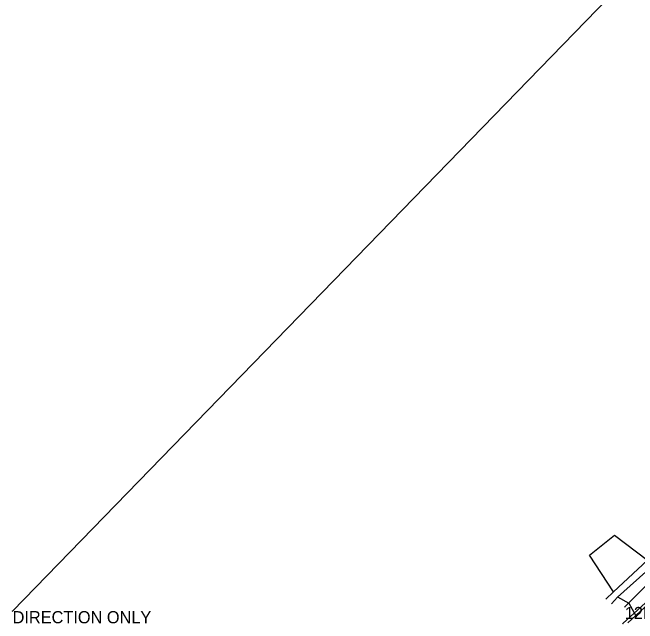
# Model space of a CAD drawing. Extents: x 1660112 to 1662239, y 668919 to 671377.
# Drawn here: x 1660996.9 to 1661253.1, y 669845.5 to 670095.9 of the extents above; entities that cross this region are included whole.
import ezdxf

# ---------------------------------------------------------------- set-up
doc = ezdxf.new("R2010")
doc.units = 0
for name, color, linetype in [('R_Horz Alg', 7, 'Continuous'), ('S_DRG_PT_SYM', 7, 'Continuous'), ('S_DRIVEWAY', 7, 'Continuous'), ('S_EDGE_PAVEMENT', 7, 'Continuous'), ('S_SANITARY_SEWER', 7, 'Continuous'), ('S_SANITARY_SEWER_ANNOT', 7, 'Continuous'), ('S_SIDE_DRAIN', 7, 'Continuous'), ('S_SIDE_DRAIN_ANNOT', 7, 'Continuous'), ('S_SIDEWALK', 7, 'Continuous'), ('S_UTL_PT_SYM', 7, 'Continuous'), ('S_WATER_UTILITIES', 7, 'Continuous')]:
    doc.layers.add(name, color=color, linetype=linetype)

msp = doc.modelspace()

# ---------------------------------------------------------------- linework, layer by layer
at = {"layer": 'R_Horz Alg'}
msp.add_arc((1655846.99, 664877.91), 7639.44, 42.561815, 45.430038, dxfattribs=at)
at = {"layer": 'S_DRG_PT_SYM'}
msp.add_lwpolyline([(1661247.92, 669852.3), (1661247.92, 669852.35), (1661247.92, 669852.3), (1661247.87, 669852.3), (1661247.92, 669852.3), (1661247.92, 669852.25), (1661247.92, 669852.3), (1661247.97, 669852.3)], dxfattribs=at)
at = {"layer": 'S_DRIVEWAY'}
for points in [[(1661243.33, 669858.48), (1661233.44, 669873.57), (1661243.64, 669881.7), (1661257.23, 669871.4)], [(1661252.39, 669848.76), (1661249.72, 669853.7), (1661244.99, 669856.24)]]:
    msp.add_lwpolyline(points, dxfattribs=at)
at = {"layer": 'S_EDGE_PAVEMENT'}
msp.add_lwpolyline([(1661249.19, 669845.77), (1661252.39, 669848.76), (1661268.86, 669863.99), (1661278.76, 669872.97), (1661288.66, 669881.95), (1661300.04, 669892.31), (1661311.42, 669902.66), (1661327.02, 669916.7), (1661339.16, 669927.65), (1661351.29, 669938.61), (1661369.17, 669954.79), (1661387.06, 669970.96), (1661398.2, 669981.35), (1661409.34, 669991.75), (1661421.08, 670002.53), (1661432.82, 670013.32), (1661449.38, 670028.66), (1661451.32, 670030.24), (1661455.87, 670040.73), (1661454.57, 670045.91), (1661454.4, 670049.73)], dxfattribs=at)
at = {"layer": 'S_SANITARY_SEWER'}
msp.add_line((1661289.08, 670151.19), (1660996.93, 669850.58), dxfattribs=at)
at = {"layer": 'S_SIDE_DRAIN'}
msp.add_line((1661247.92, 669852.3), (1661262.14, 669866.58), dxfattribs=at)
at = {"layer": 'S_SIDEWALK'}
for points in [[(1661240.13, 669855.54), (1661243.3, 669858.43), (1661257.23, 669871.4), (1661268.37, 669881.24), (1661279.52, 669891.08), (1661292, 669902.52), (1661304.47, 669913.96), (1661314.57, 669923.73), (1661328.21, 669936.13), (1661341.84, 669948.53), (1661344.15, 669950), (1661359.19, 669964.33), (1661360.75, 669962.46)], [(1661242.46, 669853.59), (1661244.91, 669856.24), (1661259.13, 669868.97), (1661270.42, 669879.12), (1661281.71, 669889.26), (1661294.12, 669900.64), (1661306.53, 669912.02), (1661317.71, 669922.4), (1661330.68, 669934.19), (1661343.64, 669945.98), (1661345.57, 669947.5), (1661360.69, 669962.51)]]:
    msp.add_lwpolyline(points, dxfattribs=at)
at = {"layer": 'S_UTL_PT_SYM'}
for points in [[(1660996.93, 669850.58), (1660996.93, 669850.63), (1660996.93, 669850.58), (1660996.88, 669850.58), (1660996.93, 669850.58), (1660996.93, 669850.53), (1660996.93, 669850.58), (1660996.98, 669850.58)], [(1661247.14, 669845.57), (1661247.14, 669845.62), (1661247.14, 669845.57), (1661247.09, 669845.57), (1661247.14, 669845.57), (1661247.14, 669845.52), (1661247.14, 669845.57), (1661247.19, 669845.57)]]:
    msp.add_lwpolyline(points, dxfattribs=at)
at = {"layer": 'S_WATER_UTILITIES'}
msp.add_line((1661247.14, 669845.57), (1661272.57, 669868.7), dxfattribs=at)

# ---------------------------------------------------------------- texts
at = {"layer": 'S_SANITARY_SEWER_ANNOT'}
msp.add_text('DIRECTION ONLY', height=5, dxfattribs=at).set_placement((1660996.93, 669845.58))
at = {"layer": 'S_SIDE_DRAIN_ANNOT'}
msp.add_text('12IN PLASTIC', height=5, dxfattribs=at).set_placement((1661247.92, 669847.3))

doc.saveas('drawing.dxf')
